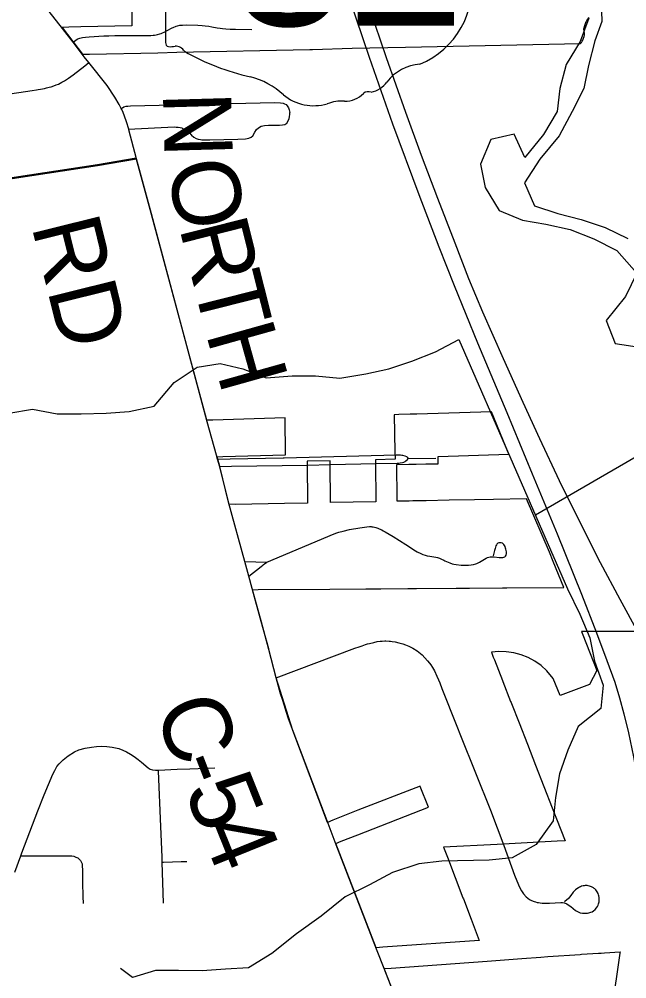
# Model space of a CAD drawing. Extents: x -6.4 to 34, y -4.2 to 22.
# Drawn here: x 3.822 to 4.329, y 18.286 to 19.085 of the extents above; entities that cross this region are included whole.
import ezdxf

# ---------------------------------------------------------------- set-up
doc = ezdxf.new("R2010")
doc.units = 0
for name, color, linetype in [('GM_X_City_Street', 7, 'Continuous'), ('GM_X_Corporation', 7, 'Continuous'), ('GM_X_County_Road', 7, 'Continuous'), ('GM_X_County_Road_Text', 7, 'Continuous'), ('GM_X_Major_River', 7, 'Continuous'), ('GM_X_Minor_River', 7, 'Continuous'), ('GM_X_State_Route', 7, 'Continuous'), ('GM_X_State_Shield', 7, 'Continuous'), ('GM_X_Township_Road', 7, 'Continuous')]:
    doc.layers.add(name, color=color, linetype=linetype)

msp = doc.modelspace()

# ---------------------------------------------------------------- linework, layer by layer
at = {"layer": 'GM_X_City_Street'}
msp.add_line((4.01022, 18.63313), (4.02871, 18.63255), dxfattribs=at)
for points in [[(3.86707, 19.06569), (3.86832, 19.06666), (3.86936, 19.06747), (3.8704, 19.06814), (3.87114, 19.06855), (3.87183, 19.06884), (3.87286, 19.06915), (3.87496, 19.0695), (3.87759, 19.06984), (3.88054, 19.07009), (3.89274, 19.07083), (3.89702, 19.07102), (3.90197, 19.07114), (3.9218, 19.07119), (3.92905, 19.07119), (3.93186, 19.07134), (3.93376, 19.07146), (3.93509, 19.07162), (3.93629, 19.07181), (3.9376, 19.07209), (3.9394, 19.07258), (3.94051, 19.07293), (3.94176, 19.0734), (3.94294, 19.07394), (3.94924, 19.07744), (3.951, 19.07826), (3.9524, 19.07881), (3.95305, 19.07906), (3.95414, 19.07934), (3.95597, 19.07971), (3.95833, 19.07992), (3.9617, 19.08), (3.97098, 19.07983), (3.97479, 19.07959), (3.9773, 19.07933), (3.98024, 19.07892), (3.98264, 19.07853), (3.98722, 19.07772), (3.98971, 19.07734), (3.99172, 19.07708), (3.99455, 19.07683), (3.99795, 19.07661), (4.00236, 19.07644), (4.01621, 19.07618)], [(4.02871, 18.63255), (4.06877, 18.64958), (4.08126, 18.65491), (4.08601, 18.65672), (4.08848, 18.65755), (4.09233, 18.65862), (4.09756, 18.65982), (4.10611, 18.66129), (4.11197, 18.66212), (4.11422, 18.66232), (4.11551, 18.6623), (4.11619, 18.66223), (4.11731, 18.66205), (4.11827, 18.66181), (4.11934, 18.6615), (4.12117, 18.66085), (4.12236, 18.66037), (4.12433, 18.65947), (4.12562, 18.65883), (4.12732, 18.6579), (4.13386, 18.65405), (4.14433, 18.6474), (4.15237, 18.64216), (4.15385, 18.64129), (4.15682, 18.63977), (4.15868, 18.63904), (4.16063, 18.6384), (4.16227, 18.63802), (4.16439, 18.63768), (4.16952, 18.63682), (4.17079, 18.63649), (4.17249, 18.63593), (4.17409, 18.63528), (4.1762, 18.63429), (4.17708, 18.63388), (4.18114, 18.63203), (4.18293, 18.63138), (4.18459, 18.63095), (4.18653, 18.63062), (4.1907, 18.63027), (4.19299, 18.63022), (4.19668, 18.63028), (4.19881, 18.63047), (4.20089, 18.63078), (4.20279, 18.63128), (4.20369, 18.6316), (4.20587, 18.63267), (4.20875, 18.63434), (4.21146, 18.63592), (4.21255, 18.63644), (4.21354, 18.63677), (4.2148, 18.63702), (4.21577, 18.63712), (4.21806, 18.63707), (4.22237, 18.63659), (4.22466, 18.6365), (4.22541, 18.63656), (4.22619, 18.63676), (4.22691, 18.63709), (4.22744, 18.63754), (4.22805, 18.63859), (4.22828, 18.63979), (4.22831, 18.64068), (4.22826, 18.64136), (4.2278, 18.64357), (4.22754, 18.64445), (4.22712, 18.64559), (4.22672, 18.64642), (4.22617, 18.64727), (4.2257, 18.64782), (4.22497, 18.64841), (4.2239, 18.64878), (4.22299, 18.64889), (4.22192, 18.64871), (4.22123, 18.64841), (4.2204, 18.64772), (4.21989, 18.64705), (4.21951, 18.64632), (4.21913, 18.64526), (4.2188, 18.64406), (4.21843, 18.64239), (4.21729, 18.63795)], [(4.01369, 18.62102), (4.02388, 18.62911), (4.02516, 18.63009), (4.02596, 18.63072), (4.0267, 18.63126), (4.02871, 18.63255)], [(3.81852, 18.37465), (3.82345, 18.38816), (3.82437, 18.39068), (3.83096, 18.40812), (3.83772, 18.42555), (3.84316, 18.43895), (3.85032, 18.45605), (3.85181, 18.45925), (3.8537, 18.46238), (3.85551, 18.46485), (3.85872, 18.46797), (3.86308, 18.4715), (3.86818, 18.47471), (3.87196, 18.47635), (3.87706, 18.47775), (3.8825, 18.47873), (3.88677, 18.47913), (3.89072, 18.47938), (3.89524, 18.47921), (3.8996, 18.47872), (3.90524, 18.47744), (3.90865, 18.47616), (3.9117, 18.47474), (3.91489, 18.47286), (3.91814, 18.47078), (3.92123, 18.46826), (3.92401, 18.46603), (3.92961, 18.46142), (3.93134, 18.46027), (3.93331, 18.4597), (3.93586, 18.45936), (3.9382, 18.45943), (3.95387, 18.46026), (3.96432, 18.46062), (3.97131, 18.46086), (3.98514, 18.46136)], [(3.94253, 18.34866), (3.94145, 18.38276), (3.94132, 18.3869), (3.94018, 18.41257), (3.93824, 18.45854), (3.9382, 18.45943)], [(4.22616, 18.39676), (4.23505, 18.372), (4.23826, 18.36396), (4.23947, 18.36136), (4.24086, 18.35885), (4.24242, 18.35651), (4.24462, 18.35395), (4.24599, 18.35275), (4.24758, 18.35165), (4.24918, 18.35086), (4.25133, 18.35011), (4.25262, 18.34973), (4.25391, 18.3494), (4.25514, 18.34916), (4.25634, 18.34898), (4.25806, 18.3488), (4.25945, 18.34869), (4.26405, 18.34881), (4.27372, 18.34937), (4.27511, 18.34924), (4.27638, 18.34897), (4.27799, 18.34839), (4.27871, 18.34802), (4.28061, 18.34682), (4.28197, 18.34583), (4.28594, 18.34272), (4.2871, 18.34198), (4.28852, 18.34122), (4.28978, 18.34074), (4.29157, 18.34039), (4.29277, 18.34026), (4.29413, 18.34028), (4.29574, 18.34041), (4.29692, 18.34064), (4.29855, 18.34111), (4.2997, 18.34161), (4.30088, 18.34234), (4.30231, 18.34351), (4.30331, 18.3447), (4.30416, 18.34593), (4.30476, 18.34709), (4.30513, 18.34818), (4.30533, 18.34888), (4.30551, 18.34974), (4.30565, 18.35133), (4.30564, 18.35253), (4.30556, 18.35337), (4.30529, 18.3548), (4.30503, 18.35567), (4.30465, 18.3567), (4.30396, 18.35802), (4.30331, 18.35905), (4.30267, 18.35985), (4.30195, 18.36059), (4.30146, 18.361), (4.3009, 18.3614), (4.29978, 18.36208), (4.29911, 18.3624), (4.29837, 18.36269), (4.29748, 18.36299), (4.29653, 18.3632), (4.29551, 18.36335), (4.29381, 18.36336), (4.293, 18.36325), (4.29213, 18.36309), (4.29095, 18.36274), (4.28999, 18.36239), (4.28915, 18.36199), (4.28824, 18.36149), (4.28696, 18.3607), (4.28572, 18.35972), (4.28492, 18.35892), (4.28398, 18.35789), (4.28338, 18.35712), (4.28251, 18.35593), (4.28187, 18.35505), (4.28073, 18.35358), (4.27961, 18.35241), (4.27891, 18.35175), (4.27667, 18.34973)], [(3.82345, 18.38816), (3.82464, 18.38816), (3.83416, 18.38816), (3.84821, 18.38808), (3.86026, 18.38811), (3.86602, 18.38813), (3.86766, 18.38782), (3.86938, 18.38707), (3.87099, 18.38632), (3.8723, 18.38522), (3.87318, 18.38413), (3.87399, 18.38299), (3.87456, 18.38142), (3.87479, 18.37952), (3.8749, 18.37659), (3.8751, 18.36588), (3.8753, 18.35419), (3.8754, 18.34843)], [(3.94145, 18.38276), (3.94238, 18.38279), (3.94986, 18.38305), (3.95727, 18.3833), (3.96195, 18.38347)]]:
    msp.add_lwpolyline(points, dxfattribs=at)
at = {"layer": 'GM_X_Corporation'}
for points in [[(3.91577, 19.10434), (3.91621, 19.07935), (3.87364, 19.07844), (3.8636, 19.07822), (3.85794, 19.07798), (3.86687, 19.06625), (3.87501, 19.05559), (3.8809, 19.05576), (3.93777, 19.05692), (3.95363, 19.05724), (4.06445, 19.05945), (4.06655, 19.05953), (4.09978, 19.06073), (4.14406, 19.06161), (4.29001, 19.06453), (4.29085, 19.06555), (4.29144, 19.06642), (4.29196, 19.06748), (4.29255, 19.06897), (4.29305, 19.07054), (4.29331, 19.07159), (4.29338, 19.07223), (4.29338, 19.07283), (4.29316, 19.07489), (4.29286, 19.07673), (4.29311, 19.07763), (4.29367, 19.07947), (4.29483, 19.08287), (4.29521, 19.08358), (4.2961, 19.08482), (4.29716, 19.08613)], [(4.35395, 18.57493), (4.29085, 18.57493), (4.29089, 18.57483), (4.292, 18.57208), (4.30362, 18.54254), (4.2976, 18.5308), (4.27303, 18.52155), (4.26733, 18.5359), (4.26197, 18.5423), (4.25727, 18.54656), (4.25209, 18.55023), (4.24651, 18.55326), (4.24061, 18.5556), (4.23448, 18.55722), (4.22819, 18.5581), (4.22184, 18.55823), (4.21578, 18.55762), (4.21735, 18.5536), (4.21826, 18.55128), (4.22499, 18.5341), (4.22535, 18.53318), (4.23181, 18.51666), (4.23216, 18.51579), (4.23249, 18.51494), (4.23881, 18.49881), (4.24572, 18.48116), (4.25263, 18.46352), (4.25953, 18.44587), (4.26645, 18.42822), (4.27723, 18.40069), (4.27048, 18.40032), (4.23056, 18.39815), (4.22061, 18.39766), (4.1759, 18.39546), (4.17911, 18.38703), (4.19205, 18.35309), (4.19238, 18.35223), (4.1988, 18.33539), (4.20555, 18.31768), (4.12519, 18.31208), (4.11966, 18.31162), (4.08602, 18.39841), (4.09057, 18.40028), (4.10448, 18.40571), (4.16325, 18.42865), (4.15642, 18.44591), (4.15628, 18.44627), (4.10449, 18.42605), (4.08366, 18.41792), (4.07921, 18.416), (4.05028, 18.4925), (4.0362, 18.53707), (4.03013, 18.56055), (4.02384, 18.58335), (4.01665, 18.60972), (4.02149, 18.60985), (4.08103, 18.61026), (4.11098, 18.61046), (4.12357, 18.61055), (4.14619, 18.6107), (4.15332, 18.61075), (4.18648, 18.61098), (4.19175, 18.61101), (4.19762, 18.61105), (4.22495, 18.61124), (4.22875, 18.61127), (4.27605, 18.61159), (4.26726, 18.63335), (4.26419, 18.64107), (4.24509, 18.68547), (4.21739, 18.68493), (4.2017, 18.68463), (4.18048, 18.68421), (4.16144, 18.68384), (4.15016, 18.68362), (4.14723, 18.68356), (4.13723, 18.68337), (4.1372, 18.6856), (4.13684, 18.71395), (4.14684, 18.71415), (4.153, 18.71427), (4.16105, 18.71443), (4.17149, 18.71465), (4.17141, 18.72065), (4.23029, 18.72263), (4.21579, 18.75782), (4.15374, 18.756), (4.14805, 18.75584), (4.13855, 18.75557), (4.13476, 18.75545), (4.13516, 18.72457), (4.13547, 18.71856), (4.11917, 18.71799), (4.11903, 18.71361), (4.11939, 18.6854), (4.11942, 18.68302), (4.10062, 18.68265), (4.08172, 18.68228), (4.08168, 18.68496), (4.08133, 18.71278), (4.08147, 18.71715), (4.06233, 18.71679), (4.06219, 18.71242), (4.06255, 18.68474), (4.06246, 18.68191), (4.04326, 18.68153), (4.00256, 18.68074), (3.99711, 18.68093), (3.98911, 18.71294), (3.98698, 18.72025), (3.99191, 18.72065), (4.04424, 18.72218), (4.04385, 18.7528), (3.98367, 18.75104), (3.97858, 18.75087), (3.93217, 18.92328), (3.9198, 18.96908), (3.88737, 18.96349), (3.77397, 18.94644)], [(4.16541, 18.19414), (4.12649, 18.29417), (4.13221, 18.29449), (4.21211, 18.30047), (4.24105, 18.30264), (4.25687, 18.30376), (4.2628, 18.30427), (4.2898, 18.30604), (4.29084, 18.3061), (4.3049, 18.30702), (4.30732, 18.30718), (4.30991, 18.30735), (4.323, 18.3082), (4.32282, 18.30701), (4.31607, 18.26071)]]:
    msp.add_lwpolyline(points, dxfattribs=at)
at = {"layer": 'GM_X_County_Road'}
for p, q in [((3.85833, 19.07711), (3.83786, 19.10316)), ((4.08633, 18.39742), (4.07958, 18.41501)), ((4.12011, 18.31042), (4.08633, 18.39742)), ((4.12693, 18.29291), (4.12011, 18.31042)), ((4.16561, 18.19358), (4.12693, 18.29291))]:
    msp.add_line(p, q, dxfattribs=at)
for points in [[(3.87642, 19.05346), (3.86707, 19.06569), (3.85833, 19.07711)], [(3.92, 18.96852), (3.91367, 18.99255), (3.91347, 18.99324), (3.91171, 18.99936), (3.91008, 19.00395), (3.90882, 19.00709), (3.90769, 19.00958), (3.9072, 19.01053), (3.9055, 19.01378), (3.90199, 19.01977), (3.89546, 19.02948), (3.88025, 19.04865), (3.87642, 19.05346)], [(3.73649, 18.94021), (3.77417, 18.94588), (3.88757, 18.96294), (3.92, 18.96852)], [(3.97898, 18.74957), (3.93237, 18.92272), (3.92, 18.96852)], [(3.98769, 18.71836), (3.98678, 18.72168), (3.97898, 18.74957)], [(3.99671, 18.68267), (3.98931, 18.71238), (3.98769, 18.71836)], [(4.01646, 18.61061), (4.01369, 18.62102), (4.01022, 18.63313), (3.99671, 18.68267)], [(4.03643, 18.53642), (4.03033, 18.56), (4.02404, 18.5828), (4.01646, 18.61061)], [(4.07958, 18.41501), (4.05048, 18.49195), (4.04675, 18.50219), (4.04499, 18.50737), (4.04182, 18.51735), (4.04012, 18.52297), (4.03643, 18.53642)]]:
    msp.add_lwpolyline(points, dxfattribs=at)
at = {"layer": 'GM_X_Major_River'}
for points in [[(4.30714, 19.09989), (4.30781, 19.08283)], [(4.297, 19.0857), (4.28982, 19.06619), (4.2781, 19.04696), (4.27283, 19.0271), (4.27057, 19.00807), (4.25923, 18.98885), (4.24372, 18.96954), (4.2346, 18.98908), (4.21537, 18.9845), (4.2067, 18.96419), (4.21052, 18.94453), (4.22228, 18.92542), (4.24177, 18.91748), (4.26116, 18.9141), (4.28133, 18.9096), (4.30119, 18.90205), (4.32034, 18.89221), (4.33702, 18.8732), (4.32757, 18.85402), (4.31132, 18.83393), (4.31892, 18.81473), (4.33906, 18.81174)], [(4.30781, 19.08283), (4.30193, 19.06683), (4.29668, 19.04621), (4.29291, 19.02715), (4.28308, 19.00796), (4.27213, 18.98761), (4.25625, 18.96828), (4.2434, 18.94865), (4.25175, 18.92947), (4.2712, 18.92305), (4.29063, 18.91815), (4.31047, 18.91136), (4.3296, 18.90227)]]:
    msp.add_lwpolyline(points, dxfattribs=at)
at = {"layer": 'GM_X_Minor_River'}
msp.add_line((4.46025, 18.79254), (4.25242, 18.67176), dxfattribs=at)
msp.add_lwpolyline([(3.8136, 18.75687), (3.83323, 18.75995), (3.85377, 18.75621), (3.87385, 18.75626), (3.89468, 18.7567), (3.91397, 18.75825), (3.93471, 18.76249), (3.95135, 18.78221), (3.9704, 18.79514), (3.98966, 18.79821), (4.0087, 18.79368), (4.02818, 18.78612), (4.04974, 18.78773), (4.06906, 18.78776), (4.08955, 18.78592), (4.11107, 18.78941), (4.13031, 18.79362), (4.1495, 18.8001), (4.16904, 18.80773), (4.18853, 18.81802), (4.27922, 18.6104), (4.2895, 18.58936), (4.29787, 18.56979), (4.30169, 18.55013), (4.30892, 18.53017), (4.30705, 18.51076), (4.28804, 18.49593), (4.27936, 18.47601), (4.27257, 18.4565), (4.26919, 18.43669), (4.26732, 18.41729), (4.25295, 18.39762), (4.23311, 18.38656), (4.21382, 18.38463), (4.17444, 18.3838), (4.15517, 18.38148), (4.13335, 18.37419), (4.11424, 18.36391), (4.09399, 18.35398), (4.07386, 18.33799), (4.05333, 18.32312), (4.03284, 18.30674), (4.01338, 18.29494), (3.99409, 18.29377), (3.9748, 18.29222), (3.95509, 18.29255), (3.93577, 18.29252), (3.91657, 18.2868), (3.90657, 18.29418)], dxfattribs=at)
at = {"layer": 'GM_X_State_Route'}
for points in [[(4.03943, 19.29261), (4.06914, 19.19055), (4.07946, 19.15729), (4.09615, 19.10582), (4.10865, 19.06869), (4.1138, 19.05317)], [(4.05333, 19.29269), (4.06416, 19.25431), (4.07696, 19.21063), (4.09161, 19.16349), (4.10429, 19.124), (4.11869, 19.08057), (4.12817, 19.05293)], [(4.1138, 19.05317), (4.13344, 18.99781), (4.15526, 18.93895), (4.17187, 18.89538), (4.1848, 18.86307), (4.20428, 18.81529), (4.22852, 18.75736), (4.24974, 18.70629), (4.2705, 18.65631), (4.29085, 18.60599), (4.30331, 18.57386)], [(4.12817, 19.05293), (4.14428, 19.0074), (4.15725, 18.97169), (4.17088, 18.93582), (4.18516, 18.89848), (4.19666, 18.86902), (4.20848, 18.84105), (4.22557, 18.80239), (4.24183, 18.76602), (4.25578, 18.73575), (4.27237, 18.7007), (4.29061, 18.66367), (4.30638, 18.63241), (4.32268, 18.60185), (4.33796, 18.57379)], [(4.30331, 18.57386), (4.31193, 18.55091), (4.31855, 18.53269), (4.32263, 18.51959), (4.3262, 18.50635), (4.32992, 18.4906), (4.33411, 18.47049), (4.33537, 18.46385), (4.33855, 18.44726), (4.34152, 18.42883), (4.34499, 18.40418), (4.34772, 18.38322), (4.35168, 18.35491), (4.357, 18.31801), (4.35971, 18.30146), (4.36246, 18.28747), (4.36516, 18.27601)]]:
    msp.add_lwpolyline(points, dxfattribs=at)
at = {"layer": 'GM_X_State_Shield'}
msp.add_line((3.94424, 19.26554), (3.94424, 19.06542), dxfattribs=at)
for centre, radius, start, end in [((4.12965, 19.11213), 0.06994, 292.30889, 8.98584), ((3.94729, 19.06498), 0.00308, 171.95839, 258.30661), ((3.94776, 19.08545), 0.02352, 267.33899, 280.60386), ((3.95257, 19.05387), 0.00848, 29.74838, 93.27175), ((4.05963, 19.23367), 0.20192, 240.41292, 257.1985), ((4.15914, 19.00924), 0.0383, 94.40312, 142.57675), ((3.99943, 18.97551), 0.06318, 47.18416, 75.83597), ((4.11061, 19.04602), 0.0226, 282.87319, 323.27711), ((4.06776, 19.05288), 0.04009, 230.70037, 286.29184), ((4.09385, 19.03789), 0.02136, 268.77702, 315.54927), ((4.11317, 19.01851), 0.00601, 65.75173, 132.64842), ((4.09092, 18.98369), 0.03294, 85.69512, 111.20995)]:
    msp.add_arc(centre, radius, start, end, dxfattribs=at)
at = {"layer": 'GM_X_Township_Road'}
for p, q in [((4.14639, 18.71904), (4.16936, 18.71939)), ((4.06257, 18.71354), (4.08178, 18.71397)), ((4.08178, 18.71397), (4.11944, 18.71479))]:
    msp.add_line(p, q, dxfattribs=at)
for points in [[(3.76747, 19.01601), (3.76837, 19.01603), (3.76967, 19.01608), (3.77047, 19.01613), (3.77143, 19.0162), (3.83305, 19.02535), (3.83655, 19.02591), (3.83799, 19.02615), (3.84009, 19.02654), (3.84322, 19.02715), (3.84492, 19.02753), (3.84725, 19.02811), (3.84879, 19.02854), (3.85097, 19.02925), (3.85315, 19.03012), (3.85493, 19.03085), (3.85775, 19.03226), (3.86, 19.03354), (3.86172, 19.03466), (3.86333, 19.03574), (3.86536, 19.03714), (3.86708, 19.03843), (3.8769, 19.04605), (3.88025, 19.04865)], [(3.9072, 19.01053), (3.90838, 19.01114), (3.9095, 19.01173), (3.91128, 19.01229), (3.91263, 19.0125), (3.91488, 19.01263), (4.035, 19.01551), (4.04007, 19.01524), (4.04214, 19.01483), (4.04324, 19.01445), (4.04461, 19.0137), (4.04565, 19.01267), (4.04659, 19.01114), (4.04724, 19.0094), (4.04774, 19.00702)], [(3.91347, 18.99324), (3.91871, 18.99351), (3.94614, 18.99497), (3.95147, 18.99507), (3.95296, 18.99499), (3.95472, 18.99479), (3.95624, 18.99455), (3.95766, 18.99422), (3.95842, 18.99391), (3.9594, 18.99352), (3.96001, 18.99321), (3.96138, 18.99237), (3.96209, 18.99185), (3.96381, 18.99036), (3.9659, 18.98825), (3.96788, 18.98654), (3.96962, 18.98551), (3.97134, 18.98494), (3.97322, 18.98454), (3.97436, 18.98439), (3.97736, 18.9843), (3.98113, 18.98437), (4.00453, 18.98505), (4.0109, 18.98529), (4.01355, 18.98572), (4.01544, 18.98655), (4.01706, 18.98778), (4.01872, 18.99061), (4.02009, 18.99292), (4.02168, 18.99445), (4.02386, 18.99567), (4.02668, 18.9964), (4.02986, 18.99647), (4.0392, 18.99652), (4.04166, 18.99675), (4.04361, 18.99711), (4.0452, 18.99819), (4.04651, 19.00015), (4.04709, 19.00217), (4.04745, 19.00362), (4.04774, 19.00564), (4.04774, 19.00702)], [(3.98769, 18.71836), (3.99792, 18.71858), (4.04209, 18.71966)], [(4.04209, 18.71966), (4.04308, 18.71968), (4.1363, 18.72211)], [(4.11944, 18.71479), (4.13734, 18.71508), (4.13851, 18.7151), (4.13985, 18.71525), (4.14163, 18.71553), (4.14279, 18.71596), (4.14388, 18.71654), (4.14453, 18.71701), (4.14575, 18.71817), (4.14639, 18.71904)], [(4.1363, 18.72211), (4.13731, 18.72213), (4.14003, 18.722), (4.14108, 18.72189), (4.14178, 18.72177), (4.14361, 18.72129), (4.14496, 18.72061), (4.14558, 18.72011), (4.14639, 18.71904)], [(3.98931, 18.71238), (3.99914, 18.71271), (4.06257, 18.71354)], [(4.03643, 18.53642), (4.10185, 18.56093), (4.10548, 18.56227), (4.10793, 18.56312), (4.11084, 18.56407), (4.11237, 18.56453), (4.1143, 18.56506), (4.11768, 18.5659), (4.12069, 18.56647), (4.12302, 18.5668), (4.12469, 18.56696), (4.12681, 18.56707), (4.12784, 18.56709), (4.13044, 18.56701), (4.1318, 18.56689), (4.13308, 18.56673), (4.13549, 18.56627), (4.13875, 18.56554), (4.14205, 18.56458), (4.14406, 18.56387), (4.14704, 18.56264), (4.15018, 18.56112), (4.15396, 18.55872), (4.15794, 18.55556), (4.16263, 18.55058), (4.16428, 18.54858), (4.16522, 18.54727), (4.16673, 18.54484), (4.16821, 18.54225), (4.17028, 18.53773), (4.17166, 18.5346), (4.1727, 18.5321), (4.17455, 18.52751), (4.18689, 18.49617), (4.18996, 18.48845), (4.21488, 18.42619), (4.22616, 18.39676)]]:
    msp.add_lwpolyline(points, dxfattribs=at)

# ---------------------------------------------------------------- texts
at = {"layer": 'GM_X_County_Road_Text'}
for s, height, rotation, p in [('N', 0.05682, 271.61031, (3.94194, 19.02383)), ('O', 0.05682, 281.73311, (3.94462, 18.96297)), ('RD', 0.056818, 283.91672, (3.83228, 18.91295)), ('R', 0.05682, 284.13044, (3.95536, 18.91149)), ('T', 0.05682, 284.16554, (3.96677, 18.8662)), ('H', 0.05682, 285.65395, (3.97758, 18.82343)), ('C', 0.05682, 289.63966, (3.93453, 18.51109)), ('-', 0.05682, 291.16722, (3.9508, 18.46559)), ('5', 0.05682, 291.75567, (3.95945, 18.44323)), ('4', 0.05682, 291.97121, (3.97251, 18.41051))]:
    msp.add_text(s, height=height, rotation=rotation, dxfattribs=at).set_placement(p)
at = {"layer": 'GM_X_State_Shield'}
msp.add_text('82', height=0.131836, dxfattribs=at).set_placement((3.9974, 19.07953))

doc.saveas('drawing.dxf')
